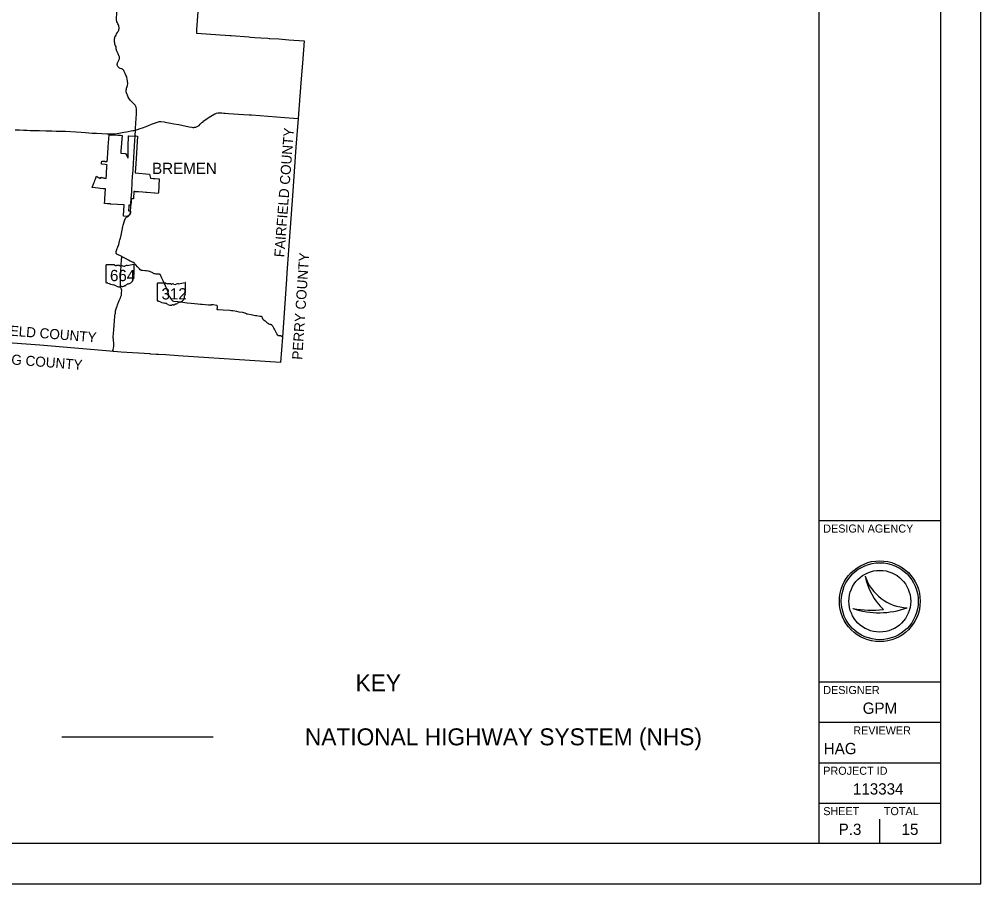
# Model space of a CAD drawing. Extents: x 1801177 to 2073177, y 78841 to 727183.
# Drawn here: x 1977949 to 2073177, y 551183 to 636851 of the extents above; entities that cross this region are included whole.
import ezdxf

# ---------------------------------------------------------------- set-up
doc = ezdxf.new("R2010")
doc.units = 0
for name, color, linetype in [('GM_X_Corporation', 7, 'Continuous'), ('GM_X_Corporation_Text', 7, 'Continuous'), ('GM_X_County', 7, 'Continuous'), ('GM_X_County_Text', 7, 'Continuous'), ('GM_X_State_Location', 7, 'Continuous'), ('GM_X_State_Route', 7, 'Continuous'), ('GM_X_State_Shield', 7, 'Continuous'), ('SH_Border', 7, 'Continuous'), ('SH_Cut_Line', 7, 'Continuous'), ('SH_Data', 7, 'Continuous'), ('UT_P_Electric', 7, 'Continuous')]:
    doc.layers.add(name, color=color, linetype=linetype)

msp = doc.modelspace()

# ---------------------------------------------------------------- linework, layer by layer
at = {"layer": 'GM_X_Corporation'}
msp.add_lwpolyline([(1988340, 618454), (1987024, 618539), (1986990, 618541), (1986971, 618542), (1986852, 618551), (1986707, 618561), (1986449, 618579), (1986419, 618581), (1986419, 618582), (1986419, 618584), (1986399, 618582), (1986403, 618671), (1986411, 618869), (1986422, 619030), (1986435, 619213), (1986449, 619392), (1986460, 619576), (1986485, 620013), (1986487, 620031), (1986487, 620037), (1986486, 620037), (1986322, 620051), (1986278, 620055), (1985970, 620085), (1985766, 620105), (1985183, 620162), (1985318, 620536), (1985324, 620550), (1985379, 620702), (1985400, 620757), (1985430, 620831), (1985481, 620962), (1985503, 621018), (1985534, 621099), (1985551, 621146), (1985608, 621296), (1985804, 621163), (1985817, 621155), (1985896, 621100), (1985982, 621117), (1985985, 621077), (1986020, 621206), (1986238, 621131), (1986336, 621122), (1986405, 621101), (1986553, 621055), (1986576, 621430), (1986604, 621816), (1986616, 622003), (1986621, 622074), (1986631, 622230), (1986635, 622283), (1986643, 622412), (1986645, 622432), (1986616, 622434), (1986450, 622447), (1986097, 622476), (1986106, 622631), (1986115, 622792), (1986203, 622785), (1986363, 622772), (1986377, 622771), (1986393, 622770), (1986424, 622767), (1986663, 622748), (1986669, 622848), (1986677, 622963), (1986681, 623028), (1986684, 623078), (1986691, 623191), (1986691, 623192), (1986713, 623504), (1986760, 624210), (1986840, 625392), (1986840, 625392), (1987076, 625371), (1987373, 625389), (1987727, 625366), (1987979, 625350), (1988128, 625341), (1988077, 624610), (1988044, 624129), (1988024, 623832), (1988007, 623587), (1988047, 623584), (1988443, 623557), (1988476, 623555), (1988483, 623554), (1988566, 623403), (1988565, 623385), (1988573, 623385), (1988580, 623384), (1988699, 623101), (1988713, 623100), (1988734, 623097), (1988734, 623097), (1988744, 623698), (1988752, 624221), (1988770, 625302), (1988770, 625302), (1988813, 625300), (1989427, 625258), (1989427, 625258), (1989429, 625282), (1989429, 625288), (1989499, 625285), (1989653, 625276), (1989653, 625276), (1989485, 622524), (1989431, 621653), (1989429, 621614), (1990857, 621511), (1990959, 621091), (1991227, 621072), (1991376, 621063), (1991380, 621062), (1991822, 621034), (1991780, 620340), (1991739, 619652), (1991725, 619590), (1991375, 619617), (1991332, 619620), (1990583, 619677), (1990483, 619683), (1990471, 619684), (1990195, 619705), (1989777, 619737), (1989765, 619738), (1989592, 619751), (1989580, 619752), (1989530, 619756), (1989518, 619757), (1989475, 619760), (1989414, 619765), (1989409, 619765), (1989389, 619767), (1989376, 619768), (1989299, 619774), (1989299, 619765), (1989296, 619711), (1989294, 619678), (1989292, 619654), (1989287, 619570), (1989286, 619543), (1989272, 619303), (1989262, 619134), (1989258, 619056), (1989133, 619066), (1989046, 619072), (1989025, 618707), (1989024, 618699), (1989021, 618640), (1989019, 618613), (1989018, 618595), (1989016, 618560), (1989012, 618501), (1989011, 618491), (1989008, 618440), (1989007, 618419), (1989007, 618411), (1988930, 618416), (1988807, 618424), (1988807, 618424), (1988803, 618365), (1988801, 618322), (1988772, 617855), (1988911, 617845), (1988971, 617841), (1988971, 617841), (1988966, 617749), (1988962, 617687), (1988962, 617685), (1988962, 617684), (1988962, 617684), (1988962, 617684), (1988962, 617683), (1988961, 617682), (1988961, 617682), (1988961, 617682), (1988961, 617681), (1988961, 617680), (1988961, 617679), (1988961, 617678), (1988958, 617649), (1988952, 617621), (1988944, 617593), (1988934, 617565), (1988922, 617539), (1988908, 617513), (1988892, 617489), (1988874, 617466), (1988854, 617445), (1988833, 617425), (1988811, 617406), (1988663, 617296), (1988268, 617331), (1988268, 617336), (1988270, 617362)], close=True, dxfattribs=at)
at = {"layer": 'GM_X_County'}
msp.add_lwpolyline([(1995639, 637582), (1995510, 635849), (1995499, 635641), (1995489, 635467), (1998790, 635243), (1998937, 635234), (2000696, 635097), (2000843, 635088), (2001274, 635043), (2001892, 635001), (2002560, 634963), (2002706, 634954), (2002764, 634944), (2003653, 634898), (2004663, 634817), (2006153, 634698), (2006000, 632497), (2005845, 630559), (2005566, 627003), (2005354, 624172), (2005008, 619347), (2004609, 613967), (2004446, 611711), (2004409, 611078), (2004013, 605355), (2003837, 602826), (2000786, 603026), (1993695, 603490), (1992479, 603593), (1991738, 603625), (1991697, 603638), (1991650, 603642), (1991603, 603640), (1991519, 603633), (1990990, 603670), (1990885, 603680), (1990876, 603680), (1988048, 603860), (1987314, 603917), (1979976, 604550), (1972730, 605097)], dxfattribs=at)
at = {"layer": 'GM_X_State_Route'}
for p, q in [((1977541, 625881), (1977961, 625877)), ((1989461, 625868), (1989479, 626182)), ((1989461, 625868), (1989768, 625958)), ((1989422, 625245), (1989425, 625297))]:
    msp.add_line(p, q, dxfattribs=at)
for points in [[(1987847, 635993), (1987816, 636165), (1987802, 636203), (1987771, 636283), (1987722, 636383), (1987676, 636483), (1987627, 636588), (1987602, 636653), (1987586, 636728), (1987576, 636797), (1987593, 637050), (1987602, 637309), (1987607, 637412), (1987621, 637490), (1987663, 638083), (1987781, 639845), (1987828, 640664)], [(1988973, 628804), (1988936, 628844), (1988860, 628936), (1988795, 629036), (1988744, 629118), (1988661, 629313), (1988629, 629400), (1988580, 629563), (1988556, 629650), (1988548, 629750), (1988549, 629823), (1988559, 629914), (1988588, 630014), (1988636, 630171), (1988666, 630298), (1988689, 630498), (1988680, 630712), (1988650, 630929), (1988613, 631090), (1988592, 631150), (1988523, 631309), (1988443, 631489), (1988354, 631679), (1988298, 631768), (1988227, 631851), (1988189, 631886), (1988153, 631910), (1988107, 631931), (1987948, 631980), (1987888, 632006), (1987838, 632040), (1987764, 632107), (1987721, 632166), (1987681, 632244), (1987665, 632291), (1987654, 632345), (1987655, 632416), (1987671, 632489), (1987695, 632543), (1987721, 632592), (1987784, 632714), (1987847, 632861), (1987871, 632938), (1987885, 633008), (1987882, 633057), (1987872, 633110), (1987856, 633163), (1987752, 633415), (1987656, 633630), (1987594, 633776), (1987570, 633837), (1987563, 633888), (1987562, 633960), (1987560, 634056), (1987546, 634115), (1987490, 634227), (1987426, 634366), (1987401, 634502), (1987388, 634603), (1987385, 634773), (1987396, 634915), (1987408, 635010), (1987431, 635094), (1987474, 635171), (1987535, 635285), (1987594, 635406), (1987665, 635527), (1987726, 635636), (1987790, 635714), (1987805, 635762), (1987823, 635835)], [(1987823, 635835), (1987824, 635840), (1987836, 635948), (1987847, 635993)], [(1989479, 626182), (1989491, 626387), (1989501, 626535), (1989557, 627463), (1989569, 627608), (1989576, 627756), (1989578, 627831), (1989576, 627908), (1989562, 627987), (1989534, 628090), (1989514, 628144), (1989487, 628207), (1989460, 628255), (1989415, 628322), (1989340, 628419), (1989270, 628496), (1989097, 628664), (1989010, 628764), (1988973, 628804)], [(1990760, 626320), (1991054, 626437), (1991648, 626653), (1991795, 626701), (1991861, 626714), (1991958, 626718), (1992303, 626679), (1992578, 626627), (1992978, 626542), (1993262, 626487), (1993742, 626404), (1994778, 626200), (1995041, 626153), (1995146, 626138), (1995230, 626136), (1995323, 626140), (1995430, 626156), (1995520, 626188), (1995639, 626238), (1995759, 626330), (1995876, 626439), (1996046, 626609), (1996116, 626666), (1996242, 626785), (1996327, 626854), (1996556, 627004), (1996677, 627082), (1996934, 627245), (1997075, 627334), (1997171, 627392), (1997318, 627486), (1997424, 627524), (1997470, 627542), (1997622, 627575), (1997764, 627577), (1998012, 627568), (1998218, 627543), (1998348, 627539), (1998686, 627514), (2000176, 627419), (2000724, 627381), (2000957, 627367), (2004264, 627127), (2005568, 627001)], [(1977961, 625877), (1978358, 625861), (1978723, 625851), (1979030, 625836), (1979211, 625832), (1979766, 625822), (1979953, 625812), (1980585, 625802), (1981190, 625784), (1981601, 625764), (1982524, 625748), (1983553, 625692), (1984097, 625657), (1984527, 625624), (1985164, 625576), (1985604, 625547), (1986671, 625487), (1986961, 625482), (1987249, 625489), (1987464, 625504), (1987818, 625564), (1988127, 625612), (1988322, 625647), (1988573, 625695), (1989205, 625812)], [(1989205, 625812), (1989294, 625828), (1989461, 625868)], [(1989443, 625556), (1989449, 625639), (1989461, 625868)], [(1989768, 625958), (1989834, 625977), (1989928, 626008), (1990173, 626095), (1990506, 626219), (1990760, 626320)], [(1989223, 621917), (1989259, 622539), (1989300, 623160), (1989399, 624833), (1989422, 625245)], [(1989425, 625297), (1989426, 625307), (1989443, 625556)], [(1989200, 621555), (1989222, 621902), (1989223, 621917)], [(1989147, 620723), (1989182, 621270), (1989200, 621555)], [(1989094, 619840), (1989100, 619939), (1989107, 620048)], [(1989107, 620048), (1989132, 620451), (1989144, 620666), (1989147, 620723)], [(1989011, 618471), (1989017, 618581), (1989049, 619099), (1989091, 619787), (1989094, 619840)], [(1988103, 613327), (1988100, 613332), (1988096, 613338), (1988088, 613344), (1988077, 613352), (1988050, 613367), (1987924, 613433), (1987821, 613484), (1987675, 613553), (1987626, 613577), (1987607, 613589), (1987587, 613605), (1987571, 613620), (1987559, 613637), (1987549, 613654), (1987543, 613667), (1987539, 613680), (1987536, 613692), (1987535, 613707), (1987535, 613718), (1987535, 613732), (1987537, 613746), (1987541, 613762), (1987545, 613777), (1987550, 613795), (1987564, 613843), (1987627, 614030), (1987723, 614309), (1987798, 614543), (1987841, 614684), (1987894, 614874), (1987927, 615001), (1987963, 615161), (1988029, 615466), (1988130, 615964), (1988206, 616317), (1988233, 616429), (1988268, 616556), (1988330, 616760), (1988371, 616885), (1988398, 616962), (1988417, 617008), (1988439, 617053), (1988463, 617096), (1988481, 617124), (1988500, 617151), (1988522, 617176), (1988545, 617200), (1988582, 617232), (1988634, 617272), (1988780, 617379), (1988818, 617410), (1988853, 617442), (1988865, 617455), (1988876, 617466), (1988896, 617492), (1988913, 617519), (1988920, 617534), (1988927, 617548), (1988939, 617579), (1988947, 617610), (1988951, 617626), (1988954, 617642), (1988961, 617690), (1988970, 617788), (1988974, 617838), (1988980, 617935), (1988993, 618171), (1989011, 618471)], [(1987315, 603915), (1987269, 603938), (1987241, 603965), (1987230, 603990), (1987228, 604014), (1987230, 604049), (1987241, 604106), (1987288, 604280), (1987305, 604419), (1987312, 604529), (1987319, 604638), (1987317, 604726), (1987308, 604830), (1987294, 604958), (1987281, 605094), (1987255, 605303), (1987252, 605367), (1987260, 605469), (1987277, 605619), (1987297, 605805), (1987315, 606011), (1987327, 606199), (1987344, 606369), (1987358, 606600), (1987374, 606853), (1987394, 607079), (1987404, 607325), (1987418, 607479), (1987446, 607627), (1987468, 607734), (1987481, 607847), (1987493, 607969), (1987508, 608058), (1987541, 608163), (1987570, 608257), (1987641, 608418), (1987692, 608564), (1987787, 608826), (1987814, 608892), (1987854, 608995), (1987913, 609123), (1987973, 609251), (1988023, 609390), (1988062, 609514), (1988082, 609594), (1988087, 609656), (1988088, 609761), (1988095, 609983), (1988095, 610012), (1988087, 610046), (1988067, 610099), (1988016, 610235), (1987994, 610309), (1987983, 610359), (1987976, 610405), (1987971, 610511), (1987975, 610712), (1987974, 610888), (1987989, 611159), (1987991, 611415), (1988009, 611849), (1988047, 612438), (1988056, 612599), (1988062, 612884), (1988074, 613032), (1988085, 613096), (1988097, 613211), (1988106, 613282), (1988107, 613312), (1988103, 613327)], [(1997584, 608428), (1997554, 608465), (1997510, 608488), (1997163, 608541), (1997034, 608543), (1996972, 608537), (1996936, 608522), (1996867, 608519), (1996691, 608530), (1996361, 608557), (1996057, 608587), (1995917, 608597), (1995642, 608616), (1994985, 608667), (1994579, 608714), (1993932, 608801), (1993655, 608835), (1993255, 608880), (1993148, 608899), (1993071, 609012), (1993000, 609129), (1992882, 609319), (1992806, 609417), (1992763, 609494), (1992748, 609569), (1992738, 609656), (1992712, 609741), (1992684, 609815), (1992641, 609938), (1992584, 610078), (1992484, 610328), (1992408, 610523), (1992317, 610703), (1992247, 610858), (1992085, 611191), (1992022, 611348), (1991989, 611423), (1991937, 611518), (1991898, 611554), (1991870, 611571), (1991829, 611583), (1991748, 611587), (1991524, 611599), (1991403, 611610), (1991340, 611625), (1991255, 611665), (1991178, 611705), (1991112, 611743), (1991029, 611782), (1990873, 611840), (1990749, 611873), (1990669, 611887), (1990512, 611911), (1990399, 611926), (1990172, 611950), (1990063, 611967), (1990034, 611975), (1990005, 611986), (1989970, 612006), (1989938, 612033), (1989857, 612127), (1989668, 612330), (1989502, 612525), (1989408, 612627), (1989354, 612681), (1989320, 612710), (1989287, 612732), (1989241, 612754), (1989117, 612803), (1989026, 612839), (1988940, 612880), (1988775, 612967), (1988475, 613138), (1988139, 613318), (1988120, 613324), (1988103, 613327)], [(1997536, 608085), (1997554, 608158), (1997572, 608241), (1997587, 608396), (1997584, 608428)], [(2001195, 607500), (2000917, 607550), (2000562, 607611), (2000504, 607629), (2000462, 607648), (2000382, 607693), (2000325, 607719), (2000280, 607732), (2000086, 607776), (1999746, 607834), (1999492, 607879), (1999090, 607945), (1998961, 607965), (1998816, 607988), (1998142, 608016), (1997648, 608046), (1997584, 608059), (1997536, 608085)], [(2001487, 607446), (2001345, 607476), (2001195, 607500)], [(2004014, 605352), (2003915, 605436), (2003866, 605457), (2003851, 605463), (2003827, 605469), (2003802, 605472), (2003753, 605474), (2003705, 605474), (2003673, 605476), (2003647, 605480), (2003626, 605483), (2003594, 605500), (2003553, 605551), (2003475, 605689), (2003402, 605816), (2003330, 605931), (2003215, 606150), (2003165, 606240), (2003065, 606425), (2003032, 606480), (2003004, 606516), (2002980, 606544), (2002969, 606555), (2002949, 606564), (2002914, 606575), (2002880, 606586), (2002816, 606599), (2002755, 606613), (2002672, 606645), (2002641, 606660), (2002545, 606729), (2002494, 606773), (2002441, 606818), (2002367, 606886), (2002301, 606934), (2002217, 606997), (2002152, 607049), (2002118, 607083), (2002093, 607118), (2002054, 607200), (2002026, 607274), (2002012, 607316), (2001994, 607351), (2001970, 607372), (2001946, 607381), (2001875, 607391), (2001771, 607406), (2001487, 607446)]]:
    msp.add_lwpolyline(points, dxfattribs=at)
at = {"layer": 'GM_X_State_Shield'}
for p, q in [((1986542, 612475), (1986542, 610774)), ((1987390, 612505), (1986569, 612505)), ((1989343, 611657), (1989343, 612547)), ((1989343, 611657), (1989343, 611657)), ((1991623, 610661), (1991623, 608960)), ((1992471, 610690), (1991651, 610690)), ((1994425, 609843), (1994425, 610732)), ((1994425, 609843), (1994425, 609843))]:
    msp.add_line(p, q, dxfattribs=at)
for centre, major_axis, start_param, end_param in [((1986574, 612479), (32.5, 0), 1.712693, 3.28349), ((1987585, 612702), (315, 0), 4.042523, 4.731795), ((1987689, 611550), (1130, 0), 1.404758, 1.657858), ((1987946, 612488), (90.8, 0), 3.836095, 5.185415), ((1988079, 612291), (189, 0), 0.950623, 2.079405), ((1988323, 612561), (227, 0), 4.081561, 5.145723), ((1988724, 611985), (598, 0), 1.699011, 2.107814), ((1988345, 614824), (2971, 0), 4.814394, 5.042369), ((1989312, 612551), (31.2, 0), 6.141152, 7.989035), ((1989455, 611285), (211, 0), 2.387724, 3.262537), ((1989336, 611592), (48.3, 0), 1.883978, 3.671073), ((1989029, 611479), (290, 0), 5.934695, 6.695948), ((1989310, 611654), (33.4, 0), 5.05454, 6.418171), ((1986574, 610771), (32.7, 0), 3.00124, 4.508301), ((1986579, 610945), (250, 0), 4.665946, 4.897461), ((1986630, 610676), (90.1, 0), 0.519207, 1.627899), ((1987768, 612205), (2146, 0), 4.195997, 4.488961), ((1987128, 610010), (671, 0), 0.823519, 1.323587), ((1988131, 610540), (227, 0), 4.691044, 5.507374), ((1988337, 610376), (63.9, 0), 1.147584, 2.315152), ((1988309, 610609), (240, 0), 4.937069, 5.64225), ((1988825, 610297), (407, 0), 1.647645, 2.488434), ((1988512, 611171), (743, 0), 5.101752, 6.440018), ((1991655, 610665), (32.5, 0), 1.712693, 3.28349), ((1992667, 610888), (315, 0), 4.042523, 4.731795), ((1992771, 609735), (1130, 0), 1.404758, 1.657858), ((1993028, 610673), (90.8, 0), 3.836095, 5.185415), ((1993161, 610477), (189, 0), 0.950623, 2.079405), ((1993405, 610747), (227, 0), 4.081561, 5.145723), ((1993806, 610171), (598, 0), 1.699011, 2.107814), ((1993427, 613010), (2971, 0), 4.814394, 5.042369), ((1994394, 610736), (31.2, 0), 6.141152, 7.989035), ((1987854, 610668), (426, 0), 4.026481, 4.996735), ((1988100, 610080), (350, 0), 1.495662, 1.94098), ((1994537, 609470), (211, 0), 2.387724, 3.262537), ((1994418, 609777), (48.3, 0), 1.883978, 3.671073), ((1994111, 609665), (290, 0), 5.934695, 6.695948), ((1994392, 609839), (33.4, 0), 5.05454, 6.418171), ((1991656, 608956), (32.7, 0), 3.00124, 4.508301), ((1991661, 609130), (250, 0), 4.665946, 4.897461), ((1991712, 608862), (90.1, 0), 0.519207, 1.627899), ((1992849, 610390), (2146, 0), 4.195997, 4.488961), ((1992210, 608196), (671, 0), 0.823519, 1.323587), ((1992936, 608853), (426, 0), 4.026481, 4.996735), ((1993182, 608265), (350, 0), 1.495662, 1.94098), ((1993213, 608726), (227, 0), 4.691044, 5.507374), ((1993418, 608561), (63.9, 0), 1.147584, 2.315152), ((1993391, 608795), (240, 0), 4.937069, 5.64225), ((1993907, 608482), (407, 0), 1.647645, 2.488434), ((1993593, 609357), (743, 0), 5.101752, 6.440018)]:
    msp.add_ellipse(centre, major_axis=major_axis, ratio=0.8, start_param=start_param, end_param=end_param, dxfattribs=at)
at = {"layer": 'SH_Border'}
for p, q in [((2057177, 555183), (2057177, 723183)), ((2057177, 587183), (2069177, 587183)), ((2057177, 571183), (2069177, 571183)), ((2057177, 567183), (2069177, 567183)), ((2057177, 563183), (2069177, 563183)), ((2057177, 559183), (2069177, 559183))]:
    msp.add_line(p, q, dxfattribs=at)
msp.add_lwpolyline([(1813177, 723183), (2069177, 723183), (2069177, 555183), (1813177, 555183)], close=True, dxfattribs=at)
at = {"layer": 'SH_Cut_Line'}
msp.add_lwpolyline([(1801177, 551183), (2073177, 551183), (2073177, 727183), (1801177, 727183)], close=True, dxfattribs=at)
at = {"layer": 'SH_Data'}
for p, q in [((2061717, 581660), (2061717, 581660)), ((2063177, 579183), (2063177, 579183)), ((2060514, 578459), (2060514, 578459)), ((2065875, 578531), (2065875, 578531)), ((2063177, 555183), (2063177, 557583)), ((2060177, 556583), (2060177, 556583))]:
    msp.add_line(p, q, dxfattribs=at)
for radius in [4000, 3814, 3814, 3058]:
    msp.add_circle((2063177, 579183), radius, dxfattribs=at)
for centre, radius, start, end in [((2066105, 583164), 4639, 198.92567, 198.93195), ((2067950, 582944), 6365, 191.63793, 191.64215), ((2066105, 583164), 4639, 198.93195, 267.16574), ((2067950, 582944), 6365, 191.64215, 226.09467), ((2062361, 588418), 10128, 259.49639, 259.49952), ((2063092, 586143), 8105, 251.45274, 251.45764), ((2063092, 586143), 8105, 251.45764, 290.08324), ((2062361, 588418), 10128, 259.49952, 276.66723)]:
    msp.add_arc(centre, radius, start, end, dxfattribs=at)
at = {"layer": 'UT_P_Electric'}
msp.add_line((1982166, 565743), (1997166, 565743), dxfattribs=at)

# ---------------------------------------------------------------- texts
at = {"layer": 'GM_X_Corporation_Text'}
msp.add_text('BREMEN', height=1120, rotation=0.00001, dxfattribs=at).set_placement((1991106, 621512))
at = {"layer": 'GM_X_County_Text'}
for s, rotation, p in [('FAIRFIELD COUNTY', 85.68928, (2004198, 613239)), ('PERRY COUNTY', 86.11607, (2005964, 603085)), ('FAIRFIELD COUNTY', 355.46053, (1972751, 605838)), ('HOCKING COUNTY', 355.51045, (1971952, 603053))]:
    msp.add_text(s, height=1000, rotation=rotation, dxfattribs=at).set_placement(p)
at = {"layer": 'GM_X_State_Location'}
for s, p in [('664', (1987234, 635025)), ('664', (1987621, 612136)), ('312', (1992395, 609391))]:
    msp.add_text(s, height=1, rotation=0.00001, dxfattribs=at).set_placement(p)
for s, p in [('s', (1987587, 635098)), ('r', (1987587, 635098)), ('s', (1987974, 612209)), ('r', (1987974, 612209)), ('s', (1992748, 609463)), ('r', (1992748, 609463))]:
    msp.add_text(s, height=1, dxfattribs=at).set_placement(p)
at = {"layer": 'GM_X_State_Shield'}
for s, p in [('664', (1986937, 610894)), ('312', (1992040, 609080))]:
    msp.add_text(s, height=1120.7, dxfattribs=at).set_placement(p)
at = {"layer": 'SH_Data'}
for s, height, p in [('DESIGN AGENCY', 800, (2057577, 585983)), ('DESIGNER', 800, (2057577, 569983)), ('GPM', 1120, (2061484, 568023)), ('REVIEWER', 800, (2060552, 565983)), ('HAG', 1120, (2057631, 564023)), ('PROJECT ID', 800, (2057577, 561983)), ('113334', 1120, (2060521, 560023)), ('SHEET', 800, (2057577, 557983)), ('TOTAL', 800, (2063577, 557983)), ('P.3', 1120, (2059105, 556023)), ('15', 1120, (2065335, 556023))]:
    msp.add_text(s, height=height, dxfattribs=at).set_placement(p)
at = {"layer": 'UT_P_Electric'}
for s, p in [('KEY', (2011259, 570251)), ('NATIONAL HIGHWAY SYSTEM (NHS)', (2006246, 564903))]:
    msp.add_text(s, height=1680, dxfattribs=at).set_placement(p)

doc.saveas('drawing.dxf')
